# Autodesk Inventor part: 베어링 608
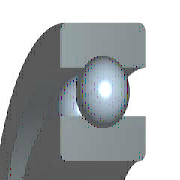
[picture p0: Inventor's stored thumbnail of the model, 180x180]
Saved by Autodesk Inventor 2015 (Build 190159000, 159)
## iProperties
IsCustomPart: 1
Created: 2012-02
Part Number: 베어링 608
Material: 강철, 연강
Description: 깊은 그루브 볼 베어링
Document SubType Name: Modeling
Standard: KS B 2023
Designer: mduedu
Standards Organization: KS
Language: ko-KR
Size Designation: 608 - 8 x 22 x 7
Categories: <MemberInstance><Categories><Category DisplayName="샤프트 부품" InternalName="7f7aeb1f-a693-4053-b835-cee3144e0d98" Mnemonic="SHFT"><Category DisplayName="베어링" Inter
Density: 7.85 g/cm^3
Appearance: Steel
Mass: 12.145 g
Surface Area: 20.0754 cm^2
Volume: 1.54714 cm^3
Author: mduedu
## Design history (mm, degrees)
sketch "스케치" dims "d0" = 3.64 (= -0.26 x WD + 0.26 x BD)
  geometry: L1 (1.68, 7.5)-(5.32, 7.5); L2 (3.5, 7.5)-(3.5, 5.68); L3 (3.5, 7.5)-(3.5, 9.32); L4 (2.148, 6.282)-(0, 6.282); L5 (0, 4)-(7, 4); L6 (2.148, 8.718)-(0, 8.718); L7 (0, 11)-(7, 11); L8 (7, 4)-(7, 6.282); L9 (4.852, 6.282)-(7, 6.282); L10 (4.852, 8.718)-(7, 8.718); L11 (7, 11)-(7, 8.718); L12 (-1.4, 0)-(8.4, 0) reference; L13 (0, -0.3)-(0, 5.3) reference
  constraints: 22 end point, 4 point on line, 2 collinear, 2 perpendicular, 2 symmetric about line, 1 midpoint, 1 parallel, 14 other
  dimensions: "d9" = 8 diameter of L5 L12 (= WD); "d11" = 22 diameter of L7 L12 (= BD); "d12" = 7 distance between parallel lines of L8 L13 (= KB); "d13" = 12.564 diameter of L9 L12 (= 0.326 x BD + 0.674 x WD)
revolve "본체" stored, may be unused: angle "d6" = 90 deg
revolve "볼" stored, may be unused: angle "d7" = 90 deg
pattern_circular "IDS_ARRAYBALL[SIMPL:T]" dims angle "d3" = 360 deg
body "Solid1"
fillet "모깎기1" dims "d1" = 0.3 (= KRS)
other parameters: "WD" = 8 [user parameter; used in 5 equation terms], "BD" = 22 [user parameter; used in 5 equation terms], "KB" = 7 [user parameter; used in 1 equation term], "KRS" = 0.3 [user parameter; used in 1 equation term], "d4" = 0, "d5" = 0, "d8" = 0, "d14" = 0, "d15" = 0, "BBA" = 0 [user parameter], "BC0" = 1370000 [user parameter], "BC" = 3250000 [user parameter], "BR" = 11 (= 0.5 x BD) [user parameter], "WR" = 4 (= 0.5 x WD) [user parameter]
